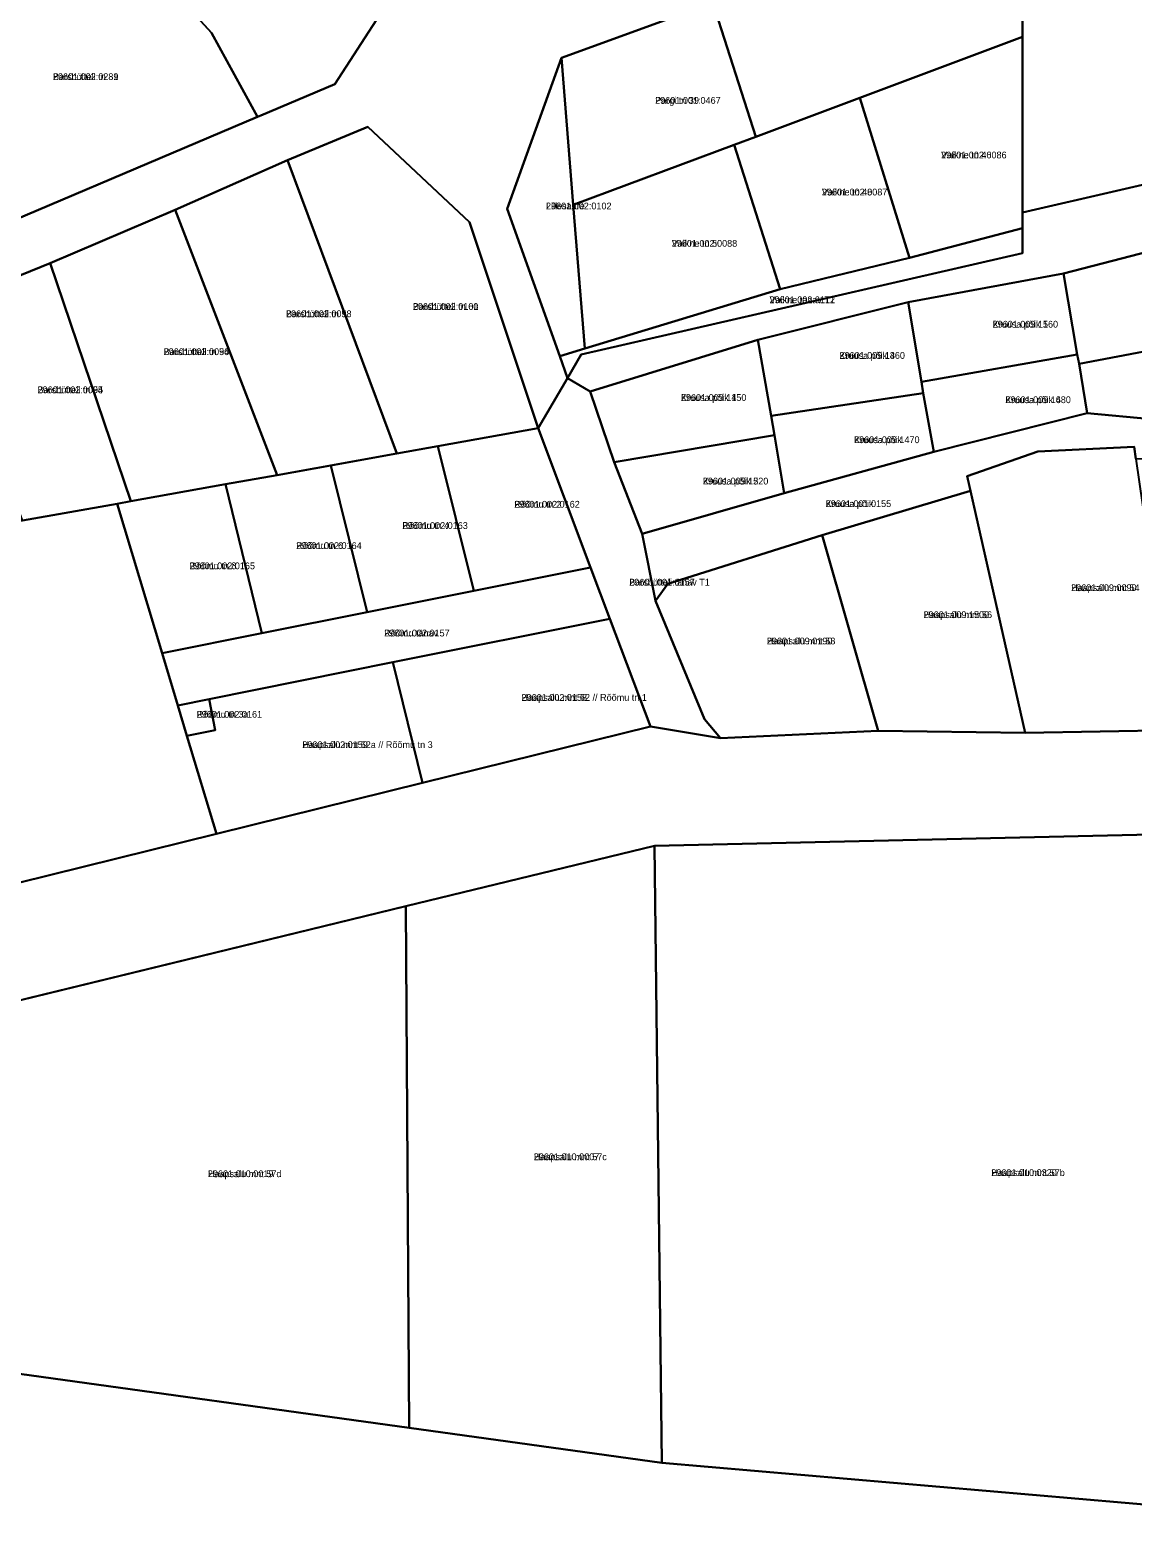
# Model space of a CAD drawing. Extents: x 518839 to 525192, y 6573164 to 6576561.
# Drawn here: x 522555.9 to 522800, y 6574299.8 to 6574633.7 of the extents above; entities that cross this region are included whole.
import ezdxf

# ---------------------------------------------------------------- set-up
doc = ezdxf.new("R2010")
doc.units = 0
for name, color, linetype in [('L_AADRESS', 7, 'Continuous'), ('PIIR', 7, 'Continuous'), ('TUNNUS', 7, 'Continuous')]:
    doc.layers.add(name, color=color, linetype=linetype)

msp = doc.modelspace()

# ---------------------------------------------------------------- linework, layer by layer
at = {"layer": 'PIIR'}
for points in [[(522775.61, 6574593.31), (522775.6, 6574658.76), (522775.6, 6574664.3), (522834.3, 6574679.53), (522819.17, 6574603.38)], [(522514.42, 6574639.52), (522576.69, 6574661.77), (522578.8, 6574656.51), (522588.95, 6574640.93), (522596.06, 6574633.1), (522606.23, 6574614.52), (522533.14, 6574583.53)], [(522707.04, 6574639.76), (522730.66, 6574648.12), (522775.6, 6574658.76), (522775.6, 6574632.24), (522739.58, 6574618.74), (522716.54, 6574610.1)], [(522676.15, 6574595.01), (522673.53, 6574627.56), (522707.04, 6574639.76), (522716.54, 6574610.1), (522711.78, 6574608.3)], [(522739.58, 6574618.74), (522775.6, 6574632.24), (522775.61, 6574593.31), (522775.61, 6574589.82), (522750.6, 6574583.28)], [(522673.53, 6574627.56), (522676.15, 6574595.01), (522678.72, 6574563.16), (522673.13, 6574561.48), (522661.49, 6574594.13)], [(522711.78, 6574608.3), (522716.54, 6574610.1), (522739.58, 6574618.74), (522750.6, 6574583.28), (522721.98, 6574576.35)], [(522612.89, 6574604.89), (522630.65, 6574612.31), (522653.13, 6574591.2), (522668.37, 6574545.52), (522646.18, 6574541.55), (522637.07, 6574539.91)], [(522676.15, 6574595.01), (522711.78, 6574608.3), (522721.98, 6574576.35), (522678.72, 6574563.16)], [(522588.01, 6574593.88), (522612.89, 6574604.89), (522637.07, 6574539.91), (522610.57, 6574535.17)], [(522560.31, 6574582.06), (522588.01, 6574593.88), (522610.57, 6574535.17), (522599.12, 6574533.12), (522578.2, 6574529.37)], [(522673.13, 6574561.48), (522678.72, 6574563.16), (522721.98, 6574576.35), (522750.6, 6574583.28), (522775.61, 6574589.82), (522775.61, 6574584.31), (522677.89, 6574561.83), (522674.85, 6574556.64)], [(522787.73, 6574561.89), (522784.67, 6574579.81), (522812.4, 6574586.98), (522815.42, 6574564.96), (522788.13, 6574559.79)], [(522536.81, 6574572.57), (522560.31, 6574582.06), (522578.2, 6574529.37), (522575.16, 6574528.82), (522554.15, 6574525.06)], [(522784.67, 6574579.81), (522787.73, 6574561.89), (522753.28, 6574555.83), (522750.3, 6574573.48)], [(522716.99, 6574565.13), (522750.3, 6574573.48), (522753.28, 6574555.83), (522753.65, 6574553.3), (522719.93, 6574548.31)], [(522679.91, 6574553.65), (522716.99, 6574565.13), (522719.93, 6574548.31), (522720.69, 6574543.98), (522685.21, 6574538.04)], [(522788.13, 6574559.79), (522815.42, 6574564.96), (522816.54, 6574565.09), (522818.41, 6574546.2), (522789.96, 6574548.87)], [(522753.65, 6574553.3), (522753.28, 6574555.83), (522787.73, 6574561.89), (522788.13, 6574559.79), (522789.96, 6574548.87), (522756, 6574540.28)], [(522679.98, 6574514.68), (522668.37, 6574545.52), (522674.85, 6574556.64), (522679.91, 6574553.65), (522685.21, 6574538.04), (522691.38, 6574522.15), (522694.38, 6574507.27), (522705.23, 6574481.06), (522708.72, 6574476.87), (522693.23, 6574479.47), (522684.26, 6574503.3)], [(522720.69, 6574543.98), (522719.93, 6574548.31), (522753.65, 6574553.3), (522756, 6574540.28), (522722.84, 6574531.16)], [(522694.38, 6574507.27), (522691.38, 6574522.15), (522722.84, 6574531.16), (522756, 6574540.28), (522789.96, 6574548.87), (522818.41, 6574546.2), (522847.82, 6574545.8), (522871.36, 6574543.38), (522908.89, 6574536.01), (522911.91, 6574536.93), (522910.14, 6574530.15), (522872.24, 6574538.13), (522870.92, 6574536), (522837.24, 6574538.59), (522800.74, 6574538.72), (522800.35, 6574541.39), (522779, 6574540.34), (522763.34, 6574534.92), (522764.07, 6574531.7), (522731.26, 6574521.82), (522697.1, 6574511.03)], [(522646.18, 6574541.55), (522668.37, 6574545.52), (522679.98, 6574514.68), (522654.11, 6574509.51)], [(522622.48, 6574537.3), (522637.07, 6574539.91), (522646.18, 6574541.55), (522654.11, 6574509.51), (522630.47, 6574504.77)], [(522720.69, 6574543.98), (522722.84, 6574531.16), (522691.38, 6574522.15), (522685.21, 6574538.04)], [(522763.34, 6574534.92), (522779, 6574540.34), (522800.35, 6574541.39), (522800.74, 6574538.72), (522809.41, 6574478.63), (522776.17, 6574478.04)], [(522599.12, 6574533.12), (522610.57, 6574535.17), (522622.48, 6574537.3), (522630.47, 6574504.77), (522607.17, 6574500.11)], [(522575.16, 6574528.82), (522578.2, 6574529.37), (522599.12, 6574533.12), (522607.17, 6574500.11), (522585.11, 6574495.7)], [(522764.07, 6574531.7), (522776.17, 6574478.04), (522743.63, 6574478.52), (522731.26, 6574521.82)], [(522413.94, 6574499.92), (522440.84, 6574504.74), (522444.78, 6574505.45), (522475.31, 6574510.92), (522501.38, 6574515.59), (522527.22, 6574520.23), (522554.15, 6574525.06), (522575.16, 6574528.82), (522585.11, 6574495.7), (522588.58, 6574484.15), (522590.6, 6574477.42), (522597.13, 6574455.7), (522420.49, 6574412.01)], [(522697.1, 6574511.03), (522731.26, 6574521.82), (522743.63, 6574478.52), (522708.72, 6574476.87), (522705.23, 6574481.06), (522694.38, 6574507.27)], [(522585.11, 6574495.7), (522607.17, 6574500.11), (522630.47, 6574504.77), (522654.11, 6574509.51), (522679.98, 6574514.68), (522684.26, 6574503.3), (522636.16, 6574493.68), (522595.51, 6574485.54), (522588.58, 6574484.15)], [(522636.16, 6574493.68), (522684.26, 6574503.3), (522693.23, 6574479.47), (522642.76, 6574466.99)], [(522590.6, 6574477.42), (522596.88, 6574478.67), (522595.51, 6574485.54), (522636.16, 6574493.68), (522642.76, 6574466.99), (522597.13, 6574455.7)], [(522588.58, 6574484.15), (522595.51, 6574485.54), (522596.88, 6574478.67), (522590.6, 6574477.42)], [(522694.1, 6574453.03), (522839.77, 6574456.33), (522845.06, 6574303.47), (522818.87, 6574305.73), (522695.74, 6574316.35)], [(522694.1, 6574453.03), (522695.74, 6574316.35), (522639.77, 6574324.13), (522639.06, 6574439.64)], [(522550.71, 6574418.14), (522639.06, 6574439.64), (522639.77, 6574324.13), (522553.54, 6574336.11), (522551.7, 6574389.29), (522551.16, 6574405.19)], [(522146.56, 6574410.62), (522180.33, 6574404.09), (522295.54, 6574381.83), (522353.2, 6574370.69), (522488.03, 6574345.21), (522553.54, 6574336.11), (522639.77, 6574324.13), (522695.74, 6574316.35), (522818.87, 6574305.73), (522817.9, 6574265.68), (522719.28, 6574270.9), (522563.91, 6574289.87), (522380.27, 6574323.44), (522276.25, 6574342.48), (522248.68, 6574347.54), (522204.59, 6574356.09), (522138.53, 6574368.89)]]:
    msp.add_lwpolyline(points, close=True, dxfattribs=at)
for points in [[(522707.04, 6574639.76), (522673.53, 6574627.56), (522661.49, 6574594.13), (522673.13, 6574561.48), (522674.85, 6574556.64), (522668.37, 6574545.52), (522653.13, 6574591.2), (522630.65, 6574612.31), (522612.89, 6574604.89), (522588.01, 6574593.88), (522560.31, 6574582.06), (522536.81, 6574572.57), (522512.48, 6574563.46), (522509.34, 6574574.89), (522508.6, 6574577.58), (522523.05, 6574582.75), (522528.34, 6574581.76), (522534.16, 6574580.68), (522533.14, 6574583.53), (522606.23, 6574614.52), (522606.92, 6574614.81), (522623.33, 6574621.73), (522639.18, 6574646.29)], [(522639.18, 6574646.29), (522623.33, 6574621.73), (522606.92, 6574614.81), (522606.23, 6574614.52), (522596.06, 6574633.1), (522588.95, 6574640.93)], [(522812.4, 6574586.98), (522784.67, 6574579.81), (522750.3, 6574573.48), (522716.99, 6574565.13), (522679.91, 6574553.65), (522674.85, 6574556.64), (522677.89, 6574561.83), (522775.61, 6574584.31), (522775.61, 6574589.82), (522775.61, 6574593.31), (522819.17, 6574603.38)], [(522839.77, 6574456.33), (522694.1, 6574453.03), (522639.06, 6574439.64), (522489.47, 6574403.23), (522353.2, 6574370.69), (522295.54, 6574381.83), (522420.49, 6574412.01), (522597.13, 6574455.7), (522642.76, 6574466.99), (522693.23, 6574479.47), (522708.72, 6574476.87), (522743.63, 6574478.52), (522776.17, 6574478.04), (522809.41, 6574478.63)]]:
    msp.add_lwpolyline(points, dxfattribs=at)

# ---------------------------------------------------------------- texts
at = {"layer": 'L_AADRESS'}
for s, p in [('Barsbütteli tn 31', (522560.92, 6574622.65)), ('Pargi tn 39', (522694.28, 6574617.39)), ('Vaikne tn 46', (522757.59, 6574605.3)), ('Vaikne tn 48', (522731.19, 6574597.09)), ('Lillesaare', (522670.11, 6574594.01)), ('Vaikne tn 50', (522697.94, 6574585.73)), ('Vaikne tänav T1', (522719.6, 6574573.23)), ('Barsbütteli tn 58', (522612.54, 6574570.13)), ('Barsbütteli tn 60', (522640.63, 6574571.74)), ('Kruusa põik 5', (522768.99, 6574567.82)), ('Barsbütteli tn 56', (522585.44, 6574561.73)), ('Kruusa põik 3', (522735.08, 6574560.9)), ('Barsbütteli tn 54', (522557.51, 6574553.29)), ('Kruusa põik 1', (522699.98, 6574551.58)), ('Kruusa põik 6', (522771.82, 6574551.09)), ('Kruusa põik 4', (522738.32, 6574542.23)), ('Kruusa põik 2', (522704.83, 6574533.07)), ('Rõõmu tn 2', (522663.08, 6574527.94)), ('Kruusa põik', (522732.03, 6574528.07)), ('Rõõmu tn 4', (522638.29, 6574523.23)), ('Rõõmu tn 6', (522614.79, 6574518.78)), ('Rõõmu tn 8', (522591.16, 6574514.3)), ('Barsbütteli tänav T1', (522688.54, 6574510.68)), ('Haapsalu mnt 54', (522786.38, 6574509.46)), ('Haapsalu mnt 56', (522753.71, 6574503.48)), ('Rõõmu tänav', (522634.26, 6574499.41)), ('Haapsalu mnt 58', (522719.01, 6574497.65)), ('Haapsalu mnt 62 // Rõõmu tn 1', (522664.68, 6574485.15)), ('Rõõmu tn 3a', (522592.73, 6574481.41)), ('Haapsalu mnt 62a // Rõõmu tn 3', (522616.14, 6574474.69)), ('Haapsalu mnt 57c', (522667.4, 6574383.41)), ('Haapsalu mnt 57d', (522595.24, 6574379.65)), ('Haapsalu mnt 57b', (522768.7, 6574379.9))]:
    msp.add_text(s, height=1.5, dxfattribs=at).set_placement(p)
at = {"layer": 'TUNNUS'}
for s, p in [('29601:002:0289', (522560.92, 6574622.65)), ('29601:001:0467', (522694.28, 6574617.39)), ('29601:002:0086', (522757.59, 6574605.3)), ('29601:002:0087', (522731.19, 6574597.09)), ('29601:002:0102', (522670.11, 6574594.01)), ('29601:002:0088', (522697.94, 6574585.73)), ('29601:002:0112', (522719.6, 6574573.23)), ('29601:002:0093', (522612.54, 6574570.13)), ('29601:002:0101', (522640.63, 6574571.74)), ('29601:009:1160', (522768.99, 6574567.82)), ('29601:002:0094', (522585.44, 6574561.73)), ('29601:009:1460', (522735.08, 6574560.9)), ('29601:002:0095', (522557.51, 6574553.29)), ('29601:009:1450', (522699.98, 6574551.58)), ('29601:009:1480', (522771.82, 6574551.09)), ('29601:009:1470', (522738.32, 6574542.23)), ('29601:009:1520', (522704.83, 6574533.07)), ('29601:002:0162', (522663.08, 6574527.94)), ('29601:001:0155', (522732.03, 6574528.07)), ('29601:002:0163', (522638.29, 6574523.23)), ('29601:002:0164', (522614.79, 6574518.78)), ('29601:002:0165', (522591.16, 6574514.3)), ('29601:001:0157', (522688.54, 6574510.68)), ('29601:009:0090', (522786.38, 6574509.46)), ('29601:009:1500', (522753.71, 6574503.48)), ('29601:002:0157', (522634.26, 6574499.41)), ('29601:009:0190', (522719.01, 6574497.65)), ('29601:002:0158', (522664.68, 6574485.15)), ('29601:002:0161', (522592.73, 6574481.41)), ('29601:002:0159', (522616.14, 6574474.69)), ('29601:010:0007', (522667.4, 6574383.41)), ('29601:010:0019', (522595.24, 6574379.65)), ('29601:010:0320', (522768.7, 6574379.9))]:
    msp.add_text(s, height=1.5, dxfattribs=at).set_placement(p)

doc.saveas('drawing.dxf')
